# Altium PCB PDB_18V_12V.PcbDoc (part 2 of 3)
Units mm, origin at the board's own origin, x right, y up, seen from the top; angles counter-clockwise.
Board outline 185 x 160 mm, 4 copper layers (Top Layer, Int1 (GND), Int2 (GND), Bottom Layer), stack 1.636 mm thick; 209 components, 100 nets, 653 pads, 1413 vias.
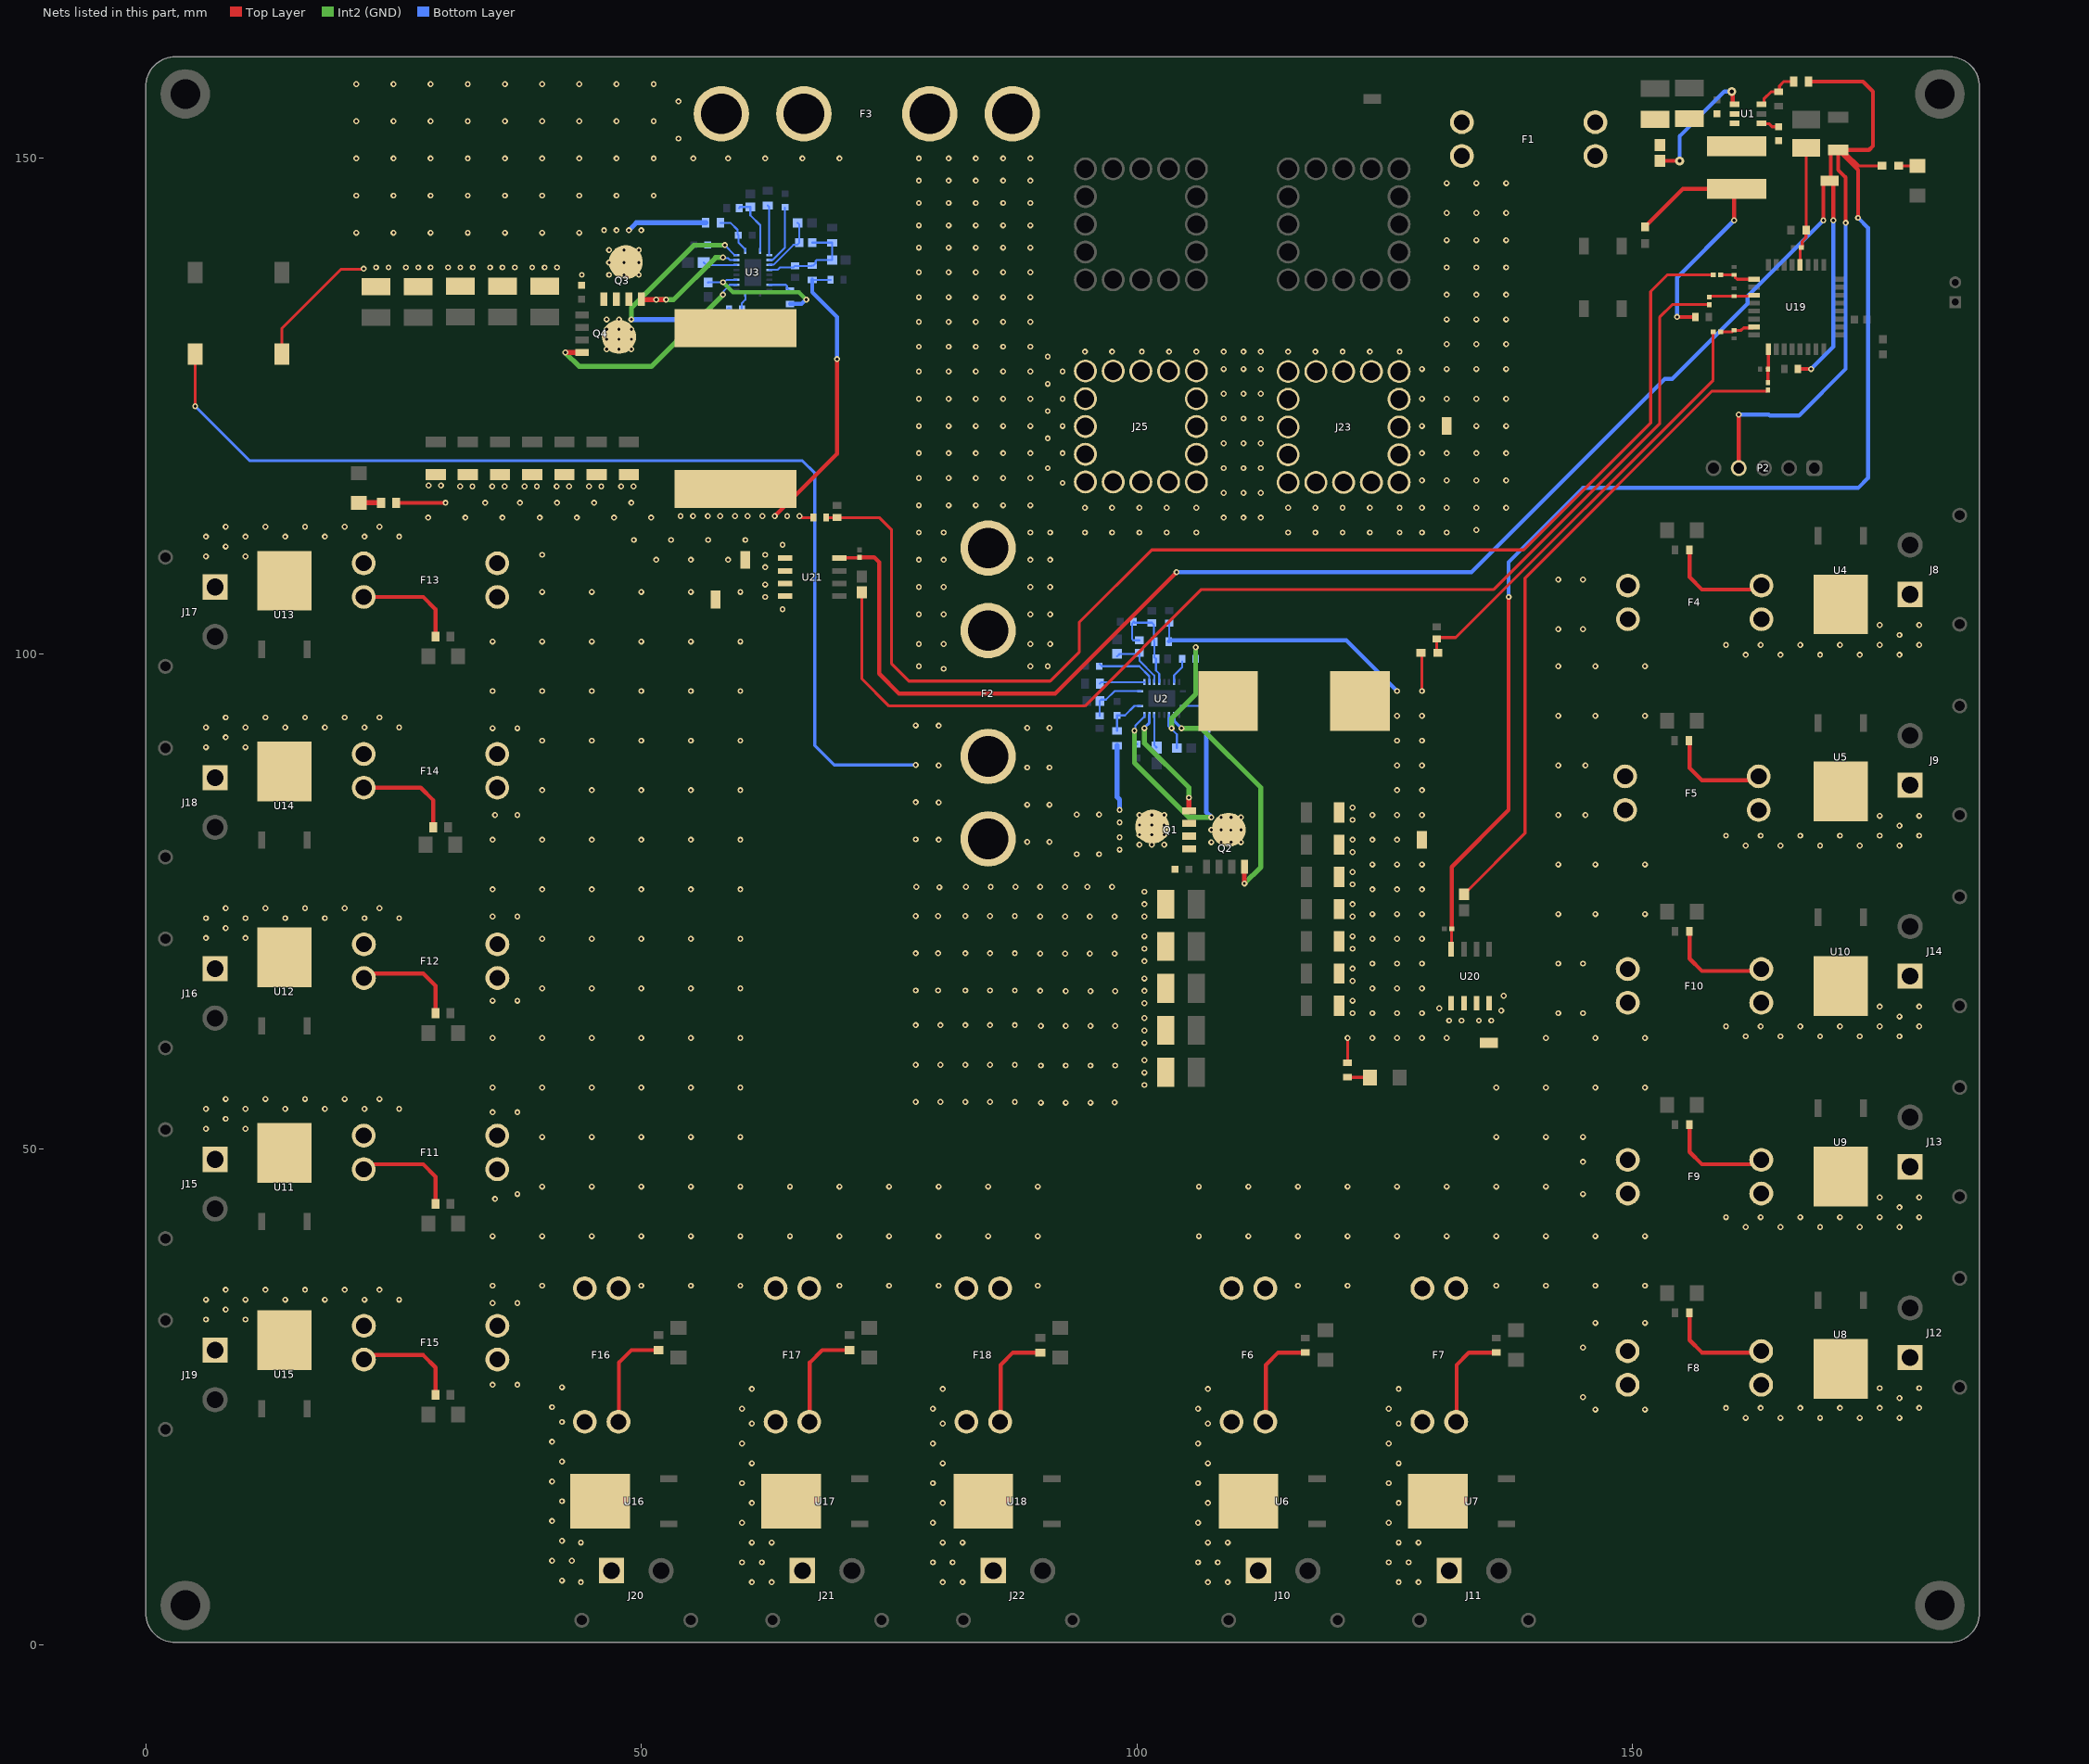
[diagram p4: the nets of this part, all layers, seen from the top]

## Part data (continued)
R3 R18: library part CMP-009-00259-1, "Fixed Resistor, Metal Glaze/thick Film, 0.1W, 140000ohm, 75V, 1% +/-Tol, 100ppm/Cel, Surface Mount, 0603", Case/Package=0603, Max Operating Temperature=155°C, Min Operating Temperature=-55°C, Power=100mW, Tolerance=1%
R5: library part CMP-009-00297-1, "CRCW FIXED RESISTOR 0603 (1608Metric) Chip Resistor ±1% ±100ppm/C 69.8kOhm 0.1W 1/10W", Case/Package=0603, Max Operating Temperature=155°C, Min Operating Temperature=-55°C, Tolerance=1%, Voltage Rating=75V
R6 R31 R32 R33 R34 R35 R36 R37: library part CMP-009-00285-1, "Res Thick Film 0603 1.6K Ohm 5% 1/10W ±200ppm/°C Molded SMD Paper T/R", Case/Package=0603, Max Operating Temperature=155°C, Min Operating Temperature=-55°C, Tolerance=5%, Voltage Rating=75V
R7 R21: library part CMP-009-00260-1, "Fixed Resistor, Thin Film, 0.1W, 7870ohm, 75V, 0.1% +/-Tol, 25ppm/Cel, Surface Mount, 0603", Case/Package=0603, Max Operating Temperature=155°C, Min Operating Temperature=-55°C, Power=100mW, Tolerance=0.1%
R8 R22: library part CMP-009-00279-1, "100mW Thick Film Resistors 75V ±100ppm/℃ ±1% 33.2kΩ 0603 Chip Resistor - Surface Mount ROHS", Case/Package=0603, Max Operating Temperature=155°C, Min Operating Temperature=-55°C, Tolerance=1%, Voltage Rating=75V
R9 R12 R25: library part CMP-009-00240-1, "Fixed Resistor, Metal Glaze/thick Film, 0.1W, 22100ohm, 75V, 1% +/-Tol, 100ppm/Cel, Surface Mount, 0603", Case/Package=0603, Max Operating Temperature=155°C, Min Operating Temperature=-55°C, Power=100mW, Tolerance=1%
R10 R11 R23 R24: library part CMP-009-00212-1, "Fixed Resistor, Metal Glaze/thick Film, 0.1W, 20000ohm, 75V, 1% +/-Tol, 100ppm/Cel, Surface Mount, 0603", Case/Package=0603, Max Operating Temperature=155°C, Min Operating Temperature=-55°C, Power=100mW, Tolerance=1%
R13: library part CMP-009-00251-1, "Fixed Resistor, Metal Glaze/thick Film, 0.1W, 165ohm, 75V, 1% +/-Tol, 100ppm/Cel, Surface Mount, 0603", Case/Package=0603, Max Operating Temperature=155°C, Min Operating Temperature=-55°C, Power=100mW, Tolerance=1%
R14 R29: library part CMP-009-00275-1, "Res Thick Film 0603 2.1 Ohm 1% 0.1W(1/10W) ±100ppm/C Molded SMD Automotive Paper T/R", Case/Package=0603, Max Operating Temperature=155°C, Min Operating Temperature=-55°C, Tolerance=1%, Voltage Rating=75V
R15 R28: library part CMP-009-00283-1, "Res Thick Film 0603 374 Ohm 1% 0.1W(1/10W) ±100ppm/C Pad SMD T/R", Case/Package=0603, Max Operating Temperature=155°C, Min Operating Temperature=-55°C, Tolerance=1%, Voltage Rating=75V
R16: library part CMP-009-00250-1, "Fixed Resistor, Thin Film, 0.1W, 4990ohm, 75V, 0.5% +/-Tol, 25ppm/Cel, Surface Mount, 0603", Case/Package=0603, Max Operating Temperature=155°C, Min Operating Temperature=-55°C, Power=100mW, Tolerance=0.5%
R17: library part CMP-009-00284-1, "Res Thick Film 0603 1.02K Ohm 1% 1/10W ±100ppm/°C Molded SMD SMD Paper T/R", Case/Package=0603, Max Operating Temperature=155°C, Min Operating Temperature=-55°C, Tolerance=1%, Voltage Rating=75V
R20 R38 R39 R40 R41 R42 R43 R44 R45: library part CMP-009-00263-1, "Fixed Resistor, Thin Film, 0.1W, 1000ohm, 75V, 0.1% +/-Tol, 50ppm/Cel, Surface Mount, 0603", Case/Package=0603, Max Operating Temperature=155°C, Min Operating Temperature=-55°C, Power=100mW, Tolerance=0.1%
R26: library part CMP-009-00287-1, "Res Thick Film 0603 158 Ohm 1% 0.1W(1/10W) ±100ppm/C Pad SMD T/R", Case/Package=0603, Max Operating Temperature=155°C, Min Operating Temperature=-55°C, Tolerance=1%, Voltage Rating=75V
R27: library part CMP-009-00197-1, "Fixed Resistor, Metal Glaze/thick Film, 0.33W, 7150ohm, 75V, 1% +/-Tol, 100ppm/Cel, Surface Mount, 0603", Case/Package=0603, Max Operating Temperature=155°C, Min Operating Temperature=-55°C, Power=250mW, Tolerance=1%
R30: library part CMP-009-00286-1, "Fixed Resistor, Metal Glaze/Thick Film, 0.1W, 1580ohm, 75V, 1% +/-Tol, Surface Mount, 0603", Case/Package=0603, Max Operating Temperature=155°C, Min Operating Temperature=-55°C, Tolerance=1%, Voltage Rating=75V
R46: library part CMP-009-00289-1, "Res Thick Film 0603 220 Ohm 5% 0.1W(1/10W) ±100ppm/C Pad SMD Automotive T/R", Case/Package=0603, Max Operating Temperature=155°C, Min Operating Temperature=-55°C, Tolerance=5%, Voltage Rating=75V
R47 R53: library part CMP-009-00288-1, "100mW Thick Film Resistors ±100ppm/℃ ±1% 10kΩ 0603 Chip Resistor - Surface Mount ROHS", Case/Package=0603, Max Operating Temperature=155°C, Min Operating Temperature=-55°C, Tolerance=1%, Voltage Rating=75V
R48: library part CMP-009-00294-1, "100mW Thick Film Resistors 75V ±100ppm/℃ ±5% 6.2kΩ 0603 Chip Resistor - Surface Mount ROHS", Case/Package=0603, Max Operating Temperature=155°C, Min Operating Temperature=-55°C, Tolerance=5%, Voltage Rating=50V
R49 R50: library part CMP-009-00293-1, "Res Thick Film 0603 2K Ohm 1% 1/10W ±100ppm/°C Molded SMD Punched Carrier T/R", Case/Package=0603, Max Operating Temperature=155°C, Min Operating Temperature=-55°C, Tolerance=1%, Voltage Rating=75V
R54 R55 R56 R57: library part CMP-009-00298-1, "Yageo RC0402FR-07150RL Resistor 0603 SMD 150 Ohm precision thick film", Case/Package=0402, Max Operating Temperature=155°C, Min Operating Temperature=-55°C, Tolerance=1%, Voltage Rating=50V
SW1 SW2: library part CMP-011-00016-1, "Slide Dip Switch, 1 Switches, SPST, Latched, 0.1A, 50VDC, Solder Terminal, Surface Mount-straight", Max Operating Temperature=85°C, Min Operating Temperature=-40°C
SW3: library part CMP-011-00018-1, "Switch Tactile OFF (ON) SPST Round Button Gull Wing 0.05A 24VDC 2.55N SMD T/R", Case/Package=SMD/SMT, Max Current Rating=20mA, Max Operating Temperature=85°C, Min Operating Temperature=-35°C
U1: library part CMP-00030-00008-3, "4V to 36V, 1A, 80-ÂµA Iq synchronous SIMPLE SWITCHERÂ® power converter 6-SOT-23 -40 to 125", Manufacturer_Name="Texas Instruments"
U2 U3: library part CMP-049-000000-3, "75V Synchronous Buck Controller With Wide Input Voltage and Duty Cycle Ranges 20-VQFN -40 to 125", Manufacturer_Name="Texas Instruments"
U4 U5 U6 U7 U8 U9 U10 U11 U12 U13 U14 U15 U16 U17 U18: library part CMP-004-00037-2, "Description", Manufacturer_Name="Diodes Inc"
U19: library part CMP-020-00027-1, "Microcontroller 32-bit ARM Cortex-M0+ RISC 64KB Flash 3.3V 32-Pin LQFP Tray", Case/Package=LQFP, Clock Frequency=48MHz, Frequency=64MHz, Max Operating Temperature=85°C, Max Supply Voltage=3.6V, Min Operating Temperature=-40°C, Min Supply Voltage=2V
U20 U21: library part CMP-056-000000-1, "AEC-Q100, Â±100-V isolated Hall-effect current sensor with internal reference 8-SOIC -40 to 125", Manufacturer_Name="Texas Instruments"

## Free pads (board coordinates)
  round 5 hole 3: 2(4,4) 2(4,156.5) 2(181,4) 2(181,156.5)

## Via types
v1: diameter 0.6, hole 0.3, Top Layer to Bottom Layer, 1411 vias
v2: diameter 0.9, hole 0.4, Top Layer to Bottom Layer, 2 vias

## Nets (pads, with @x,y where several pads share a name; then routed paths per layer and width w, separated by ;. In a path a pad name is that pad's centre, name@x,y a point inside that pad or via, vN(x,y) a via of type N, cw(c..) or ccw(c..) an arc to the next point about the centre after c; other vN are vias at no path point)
3.3V: C6.2 C7.2 C49.2 C50.2 C51.2 C52.2 J4.1 L1.1 P2.4 R2.1 R5.2 R11.2 R24.2 R53.2 U19.4 U20.8 U21.8 | length 377.5
  Top Layer w0.3: U21.8@69.974,109.655 70.022,109.702 71.953,109.702 C52.2@72,109.75 ; U20.8@131.71,70.198 131.734,70.222 131.734,72.226 C51.2@131.757,72.25 ; U19.4@166.9,139.25 166.9,140.914 166.986,141 C50.2@167.007,141 167.029,141 167.115,141.086 167.115,141.615 167.5,142 167.5,142.725 C49.2@167.525,142.75 167.525,151.05 C6.2@167.5,151.075 ; C7.2@171.568,150.507 172.825,149.25 R2.1@175.15,149.25
  Top Layer w0.4: C52.2@72,109.75 73.5,109.75 74,109.25 74,98 76,96 91.75,96 v1(104,108.25) ; C51.2@131.757,72.25 131.757,78.507 137.5,84.25 v1(137.5,105.75) ; R53.2@151.25,143.1 151.25,143.15 151.45,143.35 151.5,143.35 155.082,146.932 L1.1@160.5,146.932 160.25,146.682 v1(160.25,143.75) ; v1(154.5,134) R24.2@156.323,134 ; P2.4@160.71,118.75 v1(160.71,124.15) ; R11.2@166.677,128.75 v1(168,128.75) ; R5.2@167.75,157.75 173.25,157.75 174.25,156.75 174.25,151.25 173.85,150.85 C7.2@171.225,150.85 ; v1(169.25,143.75) 169.25,147.45 169.55,147.75 J4.1@169.87,147.75 169.95,147.75 170.25,147.45 v1(170.25,143.75) ; J4.1@170,147.75 170,150.5 170.35,150.85 C7.2@170.75,150.85 ; v1(171.5,143.5) 171.5,148.086 170.75,148.836 C7.2@170.75,150.85 ; v1(172.75,144) 172.75,148.85 C7.2@170.75,150.85
  Bottom Layer w0.4: v1(104,108.25) 133.75,108.25 153.25,127.75 154,127.75 161.606,135.356 161.606,136.106 v1(169.25,143.75) ; v1(137.5,105.75) 137.5,109.25 145,116.75 172.75,116.75 173.75,117.75 173.75,143 v1(172.75,144) ; v1(154.5,134) 154.5,138 v1(160.25,143.75) ; v1(160.71,124.15) 163.732,124.15 163.832,124.05 166.8,124.05 171.5,128.75 v1(171.5,143.5) ; v1(168,128.75) 170.25,131 v1(170.25,143.75)
3V3_CB: C1.1 U1.1 | length 1.9
  Top Layer w0.3: U1.1@163,153.55 163.045,153.505 163.76,153.505 164.065,153.2 C1.1@164.75,153.2
3V3_EN: R1.2 U1.4 | length 13.1
  Top Layer w0.4: R1.2@152.75,149.75 v2(154.75,149.75) ; v2(160,156.75) 160.096,156.654 160.096,155.529 160.175,155.45 U1.4@160.269,155.45
  Bottom Layer w0.4: v2(154.75,149.75) 154.75,152.25 159.25,156.75 v2(160,156.75)
3V3_FB: R5.1 R9.1 U1.3 | length 4.9
  Top Layer w0.3: U1.3@163,155.45 163.123,155.45 163.252,155.579 163.252,156.002 163.975,156.725 R9.1@164.75,156.725 164.824,156.799 164.824,157.324 165.25,157.75 166.025,157.75 166.25,157.975 R5.1@166.25,158
3V3_SW: C1.2 L1.2 U1.6
12V: C29.2 C30.2 C31.2 C32.2 C33.2 C34.2 C35.2 J7.1 L3.2 R20.1 R25.1 R26.2 R48.2 U21.1 U21.2 | length 35.8
  Top Layer w0.3: v1(65.967,113.901) 66.048,113.901 66.199,113.75 R48.2@67.35,113.75
  Top Layer w0.4: R20.1@25.25,115.25 v1(30.25,115.25) ; v1(63.467,113.901) 69.75,120.184 v1(69.75,129.75)
  Bottom Layer w0.2: R25.1@67.25,137.75 R26.2@69.1,137.75
  Bottom Layer w0.4: R25.1@67.25,137.75 67.25,136.5 69.75,134 v1(69.75,129.75)
  other v1: 62.5,108.75 51.5,109.5 55,109.5 58.75,109.5 62.5,110 64.25,111 49.25,111.5 53,111.5 56.75,111.5 60.5,111.5 28.5,113.75 32.25,113.75 36,113.75 39.75,113.75 43.5,113.75 47.25,113.75 51,113.75 53.967,113.901 55.217,113.901 56.717,113.901 57.967,113.901 59.467,113.901 60.717,113.901 62.217,113.901 64.717,113.901 34.25,115.25 37.75,115.25 41.5,115.25 45.25,115.25 49,115.25 31.717,116.901 32.967,116.901 34.967,116.901 36.217,116.901 38.217,116.901 39.467,116.901 41.467,116.901 42.717,116.901 44.717,116.901 45.967,116.901 47.967,116.901 49.217,116.901 28.545,116.991 29.795,116.991
12V_Fans: F15.2_1 F15.2_2 J19.P R42.2 U15.3 | length 10.5
  Top Layer w0.4: F15.2_1@22,29.25 28,29.25 29.25,28 R42.2@29.25,25.25
  other v1: 6.078,32.839 10.078,32.839 8.078,33.839 6.078,34.839 10.078,34.839 14.078,34.839 18.078,34.839 22.078,34.839 25.578,34.839 8.078,35.839 12.078,35.839 16.078,35.839 20.078,35.839 23.578,35.839
12V_PTZ: F12.2_1 F12.2_2 J16.P R39.2 U12.3 | length 10.5
  Top Layer w0.4: F12.2_1@22,67.75 28,67.75 29.25,66.5 R39.2@29.25,63.75
  other v1: 6.078,71.339 10.078,71.339 8.078,72.339 6.078,73.339 10.078,73.339 14.078,73.339 18.078,73.339 22.078,73.339 25.578,73.339 8.078,74.339 12.078,74.339 16.078,74.339 20.078,74.339 23.578,74.339
12V_RoverLab1: F13.2_1 F13.2_2 J17.P R40.2 U13.3 | length 10.5
  Top Layer w0.4: F13.2_1@22,105.75 28,105.75 29.25,104.5 R40.2@29.25,101.75
  other v1: 6.078,109.839 10.078,109.839 8.078,110.839 6.078,111.839 10.078,111.839 14.078,111.839 18.078,111.839 22.078,111.839 25.578,111.839 8.078,112.839 12.078,112.839 16.078,112.839 20.078,112.839 23.578,112.839
12V_RoverLab2: F14.2_1 F14.2_2 J18.P R41.2 U14.3 | length 10.5
  Top Layer w0.4: F14.2_1@21.75,86.5 27.75,86.5 29,85.25 R41.2@29,82.5
  other v1: 6.078,90.589 10.078,90.589 8.078,91.589 6.078,92.589 10.078,92.589 14.078,92.589 18.078,92.589 22.078,92.589 25.578,92.589 8.078,93.589 12.078,93.589 16.078,93.589 20.078,93.589 23.578,93.589
12V_S: F11.1_1 F11.1_2 F12.1_1 F12.1_2 F13.1_1 F13.1_2 F14.1_1 F14.1_2 F15.1_1 F15.1_2 F16.1_1 F16.1_2 F17.1_1 F17.1_2 F18.1_1 F18.1_2 J3.1 U21.3 U21.4
  other v1: 35,26.25 37.5,26.25 35,34.5 37.5,34.5 35,36.25 40,36.25 50,36.25 55,36.25 60,36.25 70,36.25 75,36.25 80,36.25 90,36.25 35,41.25 40,41.25 45,41.25 50,41.25 55,41.25 60,41.25 65,41.25 70,41.25 75,41.25 80,41.25 85,41.25 90,41.25 35.25,45 37.5,45.5 40,46.25 45,46.25 50,46.25 55,46.25 60,46.25 65,46.25 70,46.25 75,46.25 80,46.25 85,46.25 90,46.25 40,51.25 45,51.25 50,51.25 55,51.25 60,51.25 35,53.75 37.5,53.75 35,56.25 40,56.25 45,56.25 50,56.25 55,56.25 60,56.25 35,61.25 40,61.25 45,61.25 50,61.25 55,61.25 60,61.25 35,65 37.5,65 40,66.25 45,66.25 50,66.25 55,66.25 60,66.25 40,71.25 45,71.25 50,71.25 55,71.25 60,71.25 35,73.5 37.5,73.5 35,76.25 40,76.25 45,76.25 50,76.25 55,76.25 60,76.25 35,81.25 40,81.25 45,81.25 50,81.25 55,81.25 60,81.25 35.25,83.75 37.5,83.75 40,86.25 45,86.25 50,86.25 55,86.25 60,86.25 40,91.25 45,91.25 50,91.25 55,91.25 60,91.25 35,92.5 37.5,92.5 35,96.25 40,96.25 45,96.25 50,96.25 55,96.25 60,96.25 35,101.25 40,101.25 45,101.25 50,101.25 55,101.25 60,101.25 64.25,104.5 62.5,105.75 40,106.25 45,106.25 50,106.25 55,106.25 60,106.25 62.5,107 40,110
12V_Spare1: F16.2_1 F16.2_2 J20.P R43.2 U16.3 | length 10.5
  Top Layer w0.4: F16.2_1@47.75,22.5 47.75,28.5 49,29.75 R43.2@51.75,29.75
  other v1: 43.911,6.328 42,6.5 41,8.5 43,8.5 43.911,10.328 42,10.5 41,12.5 42,14.5 41,16.5 42,18.5 41,20.5 42,22.5 41,24 42,26
12V_Spare2: F17.2_1 F17.2_2 J21.P R44.2 U17.3 | length 10.5
  Top Layer w0.4: F17.2_1@67,22.5 67,28.5 68.25,29.75 R44.2@71,29.75
  other v1: 61.161,6.328 63.161,6.328 60.161,8.328 62.161,8.328 61.161,10.328 63.161,10.328 60.161,12.328 61.161,14.328 60.161,16.328 61.161,18.328 60.161,20.328 61.161,22.328 60.161,23.828 61.161,25.828
12V_Spare3: F18.2_1 F18.2_2 J22.P R45.2 U18.3 | length 10.5
  Top Layer w0.4: F18.2_1@86.25,22.25 86.25,28.25 87.5,29.5 R45.2@90.25,29.5
  other v1: 80.411,6.328 82.411,6.328 79.411,8.328 81.411,8.328 80.411,10.328 82.411,10.328 79.411,12.328 80.411,14.328 79.411,16.328 80.411,18.328 79.411,20.328 80.411,22.328 79.411,23.828 80.411,25.828
12V_USB_HUB: F11.2_1 F11.2_2 J15.P R38.2 U11.3 | length 10.5
  Top Layer w0.4: F11.2_1@22,48.5 28,48.5 29.25,47.25 R38.2@29.25,44.5
  other v1: 6.078,52.089 10.078,52.089 8.078,53.089 6.078,54.089 10.078,54.089 14.078,54.089 18.078,54.089 22.078,54.089 25.578,54.089 8.078,55.089 12.078,55.089 16.078,55.089 20.078,55.089 23.578,55.089
18V: C8.2 C9.2 C10.2 C11.2 C12.2 C13.2 C14.2 J5.1 L2.2 R6.1 R12.1 R13.1 R47.2 U20.1 U20.2 | length 33.5
  Top Layer w0.3: R6.1@121.25,58.725 v1(121.25,61.25) ; R47.2@128.65,100.125 128.75,100.025 v1(128.75,96.25)
  Bottom Layer w0.2: R12.1@103.225,101.25 103.25,101.275 R13.1@103.25,103.125
  Bottom Layer w0.4: R12.1@103.225,101.25 103.225,101.252 103.35,101.377 121.123,101.377 v1(126.25,96.25)
  other v1: 123.75,61.25 126.25,61.25 128.75,61.25 131.25,61.25 131.5,63 132.75,63 121.75,63.75 123.75,63.75 126.25,63.75 128.75,63.75 130.5,64.25 121.75,65 123.75,66.25 126.25,66.25 128.75,66.25 121.75,67 121.75,68.25 123.75,68.75 126.25,68.75 128.75,68.75 121.75,70.25 123.75,71.25 126.25,71.25 128.75,71.25 121.75,71.5 121.75,73.5 123.75,73.75 126.25,73.75 128.75,73.75 121.75,74.75 123.75,76.25 126.25,76.25 128.75,76.25 121.75,76.75 121.75,78 123.75,78.75 126.25,78.75 128.75,78.75 121.75,80 121.75,81.25 123.75,81.25 126.25,81.25 121.75,83.25 123.75,83.75 126.25,83.75 128.75,83.75 121.75,84.5 126.25,86.25 128.75,86.25 126.25,88.75 128.75,88.75 126.25,91.25 128.75,91.25 126.25,93.75 128.75,93.75
18V_JETSON: F5.2_1 F5.2_2 J9.P R32.2 U5.3 | length 10.5
  Top Layer w0.4: R32.2@155.75,91.25 155.75,88.5 157,87.25 F5.2_1@163,87.25
  other v1: 161.422,80.661 164.922,80.661 168.922,80.661 172.922,80.661 176.922,80.661 159.422,81.661 162.922,81.661 166.922,81.661 170.922,81.661 174.922,81.661 178.922,81.661 176.922,82.661 174.922,83.661 178.922,83.661
18V_NUC: F4.2_1 F4.2_2 J8.P R31.2 U4.3 | length 10.5
  Top Layer w0.4: R31.2@155.75,110.5 155.75,107.75 157,106.5 F4.2_1@163,106.5
  other v1: 161.422,99.911 164.922,99.911 168.922,99.911 172.922,99.911 176.922,99.911 159.422,100.911 162.922,100.911 166.922,100.911 170.922,100.911 174.922,100.911 178.922,100.911 176.922,101.911 174.922,102.911 178.922,102.911
18V_S: F4.1_1 F4.1_2 F5.1_1 F5.1_2 F6.1_1 F6.1_2 F7.1_1 F7.1_2 F8.1_1 F8.1_2 F9.1_1 F9.1_2 F10.1_1 F10.1_2 J6.1 U20.3 U20.4
  other v1: 146.25,23.75 151.25,23.75 145,25 145,30 146.25,32.5 151.25,32.5 116.25,36.25 121.25,36.25 136.25,36.25 141.25,36.25 146.25,36.25 151.25,36.25 106.25,41.25 111.25,41.25 116.25,41.25 121.25,41.25 126.25,41.25 131.25,41.25 136.25,41.25 141.25,41.25 146.25,41.25 151.25,41.25 145,45.5 106.25,46.25 111.25,46.25 116.25,46.25 121.25,46.25 126.25,46.25 131.25,46.25 136.25,46.25 141.25,46.25 145,48.75 136.25,51.25 141.25,51.25 145,51.25 136.25,56.25 141.25,56.25 146.25,56.25 151.25,56.25 141.25,61.25 146.25,61.25 151.25,61.25 134.5,63 135.75,63 142.5,63.75 145,63.75 136.75,64 137,65.5 142.5,68.75 145,68.75 142.5,73.75 146.25,73.75 151.25,73.75 142.5,78.75 146.25,78.75 151.25,78.75 142.5,83.75 145.25,83.75 142.5,88.75 145.25,88.75 142.5,93.75 146.25,93.75 151.25,93.75 142.5,98.75 146.25,98.75 151.25,98.75 142.5,102.5 145,102.5 142.5,107.5 145,107.5
18V_Spare1: F6.2_1 F6.2_2 J10.P R33.2 U6.3 | length 10.5
  Top Layer w0.4: F6.2_1@113,22.25 113,28.25 114.25,29.5 R33.2@117,29.5
  other v1: 107.161,6.328 109.161,6.328 106.161,8.328 108.161,8.328 107.161,10.328 109.161,10.328 106.161,12.328 107.161,14.328 106.161,16.328 107.161,18.328 106.161,20.328 107.161,22.328 106.161,23.828 107.161,25.828
18V_Spare2: F7.2_1 F7.2_2 J11.P R34.2 U7.3 | length 10.5
  Top Layer w0.4: F7.2_1@132.25,22.25 132.25,28.25 133.5,29.5 R34.2@136.25,29.5
  other v1: 126.411,6.328 128.411,6.328 125.411,8.328 127.411,8.328 126.411,10.328 128.411,10.328 125.411,12.328 126.411,14.328 125.411,16.328 126.411,18.328 125.411,20.328 126.411,22.328 125.411,23.828 126.411,25.828
18V_Spare3: F8.2_1 F8.2_2 J12.P R35.2 U8.3 | length 10.5
  Top Layer w0.4: R35.2@155.75,33.5 155.75,30.75 157,29.5 F8.2_1@163,29.5
  other v1: 161.422,22.911 164.922,22.911 168.922,22.911 172.922,22.911 176.922,22.911 159.422,23.911 162.922,23.911 166.922,23.911 170.922,23.911 174.922,23.911 178.922,23.911 176.922,24.911 174.922,25.911 178.922,25.911
18V_Spare4: F9.2_1 F9.2_2 J13.P R36.2 U9.3 | length 10.5
  Top Layer w0.4: R36.2@155.75,52.5 155.75,49.75 157,48.5 F9.2_1@163,48.5
  other v1: 161.422,42.161 164.922,42.161 168.922,42.161 172.922,42.161 176.922,42.161 159.422,43.161 162.922,43.161 166.922,43.161 170.922,43.161 174.922,43.161 178.922,43.161 176.922,44.161 174.922,45.161 178.922,45.161
18V_Spare5: F10.2_1 F10.2_2 J14.P R37.2 U10.3 | length 10.5
  Top Layer w0.4: R37.2@155.75,72 155.75,69.25 157,68 F10.2_1@163,68
  other v1: 161.422,61.411 164.922,61.411 168.922,61.411 172.922,61.411 176.922,61.411 159.422,62.411 162.922,62.411 166.922,62.411 170.922,62.411 174.922,62.411 178.922,62.411 176.922,63.411 174.922,64.411 178.922,64.411
24V: F1.1_1 F1.1_2 F2.1_1 F2.1_2 F3.1_1 F3.1_2 J1.1 J23.1 J23.2 J23.3 J23.4 J23.5 J23.6 J23.7 J23.8 J23.9 J23.10 J23.11 J23.12 J23.13 J23.14 J23.15 J23.16 J25.1 J25.2 J25.3 J25.4 J25.5 J25.6 J25.7 J25.8 J25.9 J25.10 J25.11 J25.12 J25.13 J25.14 J25.15 J25.16
  other v1: 80.5,98.5 78,98.75 89.25,98.75 91,98.75 78,101 80.5,101 89.25,101 91.25,101 78,104 80.5,104 89.25,104 91.25,104 78,106.75 80.5,106.75 89.25,106.75 91.25,106.75 78,109.5 80.5,109.5 89.25,109.5 91.25,109.5 78,112.25 80.5,112.25 89.25,112.25 91.25,112.25 94.75,112.25 97.5,112.25 100.25,112.25 103,112.25 106,112.25 115.25,112.25 118,112.25 120.75,112.25 123.5,112.25 126.5,112.25 128.75,112.25 131.25,112.25 134.25,112.5 108.75,113.75 110.75,113.75 112.5,113.75 94.75,114.75 97.5,114.75 100.25,114.75 103,114.75 106,114.75 115.25,114.75 118,114.75 120.75,114.75 123.5,114.75 126.5,114.75 128.75,114.75 131.25,114.75 134.25,114.75 137.25,114.75 78,115 81,115 83.75,115 86.5,115 89.25,115 108.75,116.25 110.75,116.25 112.5,116.25 92.5,117.25 128.75,117.5 131.25,117.5 134.25,117.5 137.25,117.5 78,117.75 81,117.75 83.75,117.75 86.5,117.75 89.25,117.75 91,118.75 108.75,118.75 110.75,118.75 112.5,118.75 78,120.25 81,120.25 83.75,120.25 86.5,120.25 89.25,120.25 92.5,120.25 128.75,120.25 131.25,120.25 134.25,120.25 137.25,120.25 108.75,121.25 110.75,121.25 112.5,121.25 91,121.75 78,123 81,123 83.75,123 86.5,123 89.25,123 92.5,123 128.75,123 134.25,123 137.25,123 108.75,123.75 110.75,123.75 112.5,123.75 91,124.5 78,125.75 81,125.75 83.75,125.75 86.5,125.75 89.25,125.75 92.5,125.75 128.75,125.75 131.25,125.75 134.25,125.75 137.25,125.75 108.75,126.25 110.75,126.25 112.5,126.25 91,127.25 78,128.5 81,128.5 83.75,128.5 86.5,128.5 89.25,128.5 92.5,128.5 108.75,128.75 110.75,128.75 112.5,128.75 128.75,128.75 131.25,128.75 134.25,128.75 137.25,128.75 91,130 94.75,130.5 97.5,130.5 100.5,130.5 103.25,130.5 106,130.5 108.75,130.5 110.75,130.5 112.5,130.5 115.25,130.5 118,130.5 120.75,130.5 123.5,130.5 126.5,130.5 78,131 81,131 83.75,131 86.5,131 89.25,131 131.25,131.25 134.25,131.25 137.25,131.25 78,133.5 81,133.5 83.75,133.5 86.5,133.5 89.25,133.5 131.25,133.75 134.25,133.75 137.25,133.75 78,136 81,136 83.75,136 86.5,136 89.25,136 131.25,136.25 134.25,136.25 137.25,136.25 78,138.5 81,138.5 83.75,138.5 86.5,138.5 89.25,138.5 131.25,139 134.25,139 137.25,139 78,141 81,141 83.75,141 86.5,141 89.25,141 131.25,141.75 134.25,141.75 137.25,141.75 78,143.25 81,143.25 83.75,143.25 86.5,143.25 89.25,143.25 131.25,144.5 134.25,144.5 137.25,144.5 78,145.5 81,145.5 83.75,145.5 86.5,145.5 89.25,145.5 131.25,147.5 134.25,147.5 137.25,147.5 78,147.75 81,147.75 83.75,147.75 86.5,147.75 89.25,147.75 78,150 81,150 83.75,150 86.5,150 89.25,150
24V_BUCK: C3.1 C4.1 C5.2 F1.2_1 F1.2_2 R1.1 U1.5
24V_BUCK12: C42.1 C43.1 C44.1 C45.1 C46.1 C47.1 F3.2_1 F3.2_2 Q3.5-6-7-8 R29.1 SW2.1 | length 21.4
  Top Layer w0.3: SW2.1@13.75,130.25 13.75,132.871 19.693,138.814 21.943,138.814 v1(22,138.871)
  Bottom Layer w0.5: v1(48.75,142.75) 49.5,143.5 R29.1@56.5,143.5
  other v1: 44,138.25 46.75,138.25 48.25,138.25 49.75,138.25 23.25,139 24.5,139 26.25,139 27.5,139 28.75,139 30.5,139 31.75,139 33,139 34.75,139 36,139 37.25,139 39,139 40.25,139 41.5,139 46.75,139.5 48.25,139.5 49.75,139.5 46.75,140.75 48.25,140.75 49.75,140.75 21.25,142.5 25,142.5 28.75,142.5 32.5,142.5 36.25,142.5 40,142.5 43.75,142.5 46.25,142.75 47.5,142.75 50,142.75 21.25,146.25 25,146.25 28.75,146.25 32.5,146.25 36.25,146.25 40,146.25 43.75,146.25 47.5,146.25 51.25,146.25 21.25,150 25,150 28.75,150 32.5,150 36.25,150 40,150 43.75,150 47.5,150 51.25,150 55.25,150 58.75,150 62.5,150 66.25,150 70,150 53.75,152 21.25,153.75 25,153.75 28.75,153.75 32.5,153.75 36.25,153.75 40,153.75 43.75,153.75 47.5,153.75 51.25,153.75 53.75,155.75 21.25,157.5 25,157.5 28.75,157.5 32.5,157.5 36.25,157.5 40,157.5 43.75,157.5 47.5,157.5 51.25,157.5
24V_BUCK18: C19.1 C20.1 C21.1 C22.1 C23.1 C24.1 F2.2_1 F2.2_2 Q1.5-6-7-8 R14.1 SW1.1 | length 115.6
  Top Layer w0.3: v1(5,125) SW1.1@5,130.25
  Bottom Layer w0.3: v1(5,125) 10.5,119.5 66.25,119.5 67.5,118.25 67.5,90.75 69.462,88.788 v1(77.685,88.788)
  Bottom Layer w0.5: R14.1@98,90.75 98,85.55 98.25,85.3 v1(98.25,84.25)
  other v1: 90.315,54.712 92.815,54.712 95.315,54.712 97.75,54.75 77.685,54.788 80.185,54.788 82.685,54.788 85.185,54.788 87.685,54.788 100.75,56.5 100.75,57.75 90.315,58.462 92.815,58.462 95.315,58.462 97.815,58.462 77.685,58.538 80.185,58.538 82.685,58.538 85.185,58.538 87.685,58.538 100.75,59 100.75,60.75 100.75,62 90.315,62.462 92.815,62.462 95.315,62.462 97.815,62.462 77.685,62.538 80.185,62.538 82.685,62.538 85.185,62.538 87.685,62.538 100.75,63.25 100.75,64.75 92.815,65.962 95.315,65.962 97.815,65.962 90.25,66 100.75,66 77.685,66.038 79.935,66.038 82.685,66.038 85.185,66.038 87.685,66.038 100.75,67.25 100.75,69 90.25,69.75 92.75,69.75 95.25,69.75 97.75,69.75 77.685,69.788 79.935,69.788 82.685,69.788 85.185,69.788 87.685,69.788 100.75,70.25 100.75,71.5 90.25,73.5 92.75,73.5 95.25,73.5 97.75,73.5 100.75,73.5 77.685,73.538 79.935,73.538 82.685,73.538 85.185,73.538 87.685,73.538 100.75,74.75 100.75,76 80.065,76.462 77.75,76.5 82.75,76.5 85.25,76.5 87.75,76.5 90.25,76.5 92.75,76.5 95,76.5 97.5,76.5 93.935,79.788 96.185,79.788 98.25,80.25 100.25,80.75 101.5,80.75 102.75,80.75 88.935,81.038 91.185,81.038 80,81.25 77.685,81.288 98.25,81.5 100.25,81.75 101.5,81.75 102.75,81.75 100.25,82.75 101.5,82.75 102.75,82.75 98.25,83 100.25,83.75 101.5,83.75 102.75,83.75 93.935,83.788 96.185,83.788 88.935,84.788 91.185,84.788 80,85 77.685,85.038 88.935,88.538 91.185,88.538 80,88.75 88.935,92.538 91.185,92.538 80,92.75 77.685,92.788
B3.3V_LED: D1.2 R2.2 | length 1.9
  Top Layer w0.3: R2.2@176.85,149.25 D1.2@178.75,149.25
B12_Current: C56.2 R57.2 U19.11 | length 4.6
  Top Layer w0.3: R57.2@157.75,136 157.75,136.025 157.825,136.1 C56.2@160.25,136.1 161.8,136.1 161.9,136.2 U19.11@162.25,136.2
B12_Current_In: R52.2 R57.1 | length 118.2
  Top Layer w0.3: R52.2@72.25,106.199 72.25,97.5 75,94.75 94.75,94.75 106.5,106.5 136,106.5 152.75,123.25 152.75,134 154,135.25 R57.1@157.563,135.25
B12_Voltage: C54.2 R55.2 U19.9 | length 3.7
  Top Layer w0.3: R55.2@158.875,138.25 160.3,138.25 160.35,138.2 160.35,138 160.55,137.8 U19.9@162.25,137.8
B12_Voltage_In: R48.1 R50.2 R55.1 | length 130.7
  Top Layer w0.3: R48.1@68.65,113.75 R50.2@69.75,113.75 74,113.75 75.25,112.5 75.25,99 77,97.25 91.25,97.25 94.175,100.175 94.175,103.175 101.5,110.5 139,110.5 151.817,123.317 151.817,136.567 153.5,138.25 R55.1@158.125,138.25
B12V_BST: R19.1 U3.17 | length 3.4
  Bottom Layer w0.2: R19.1@56.301,139.5 56.551,139.25 U3.17@59.6,139.25
B12V_COMP: C38.1 C41.1 U3.4 | length 6.1
  Bottom Layer w0.2: U3.4@62.9,139.25 62.92,139.27 63.33,139.27 65.342,141.282 65.732,141.282 C41.1@65.95,141.5 65.95,143.324 C38.1@65.774,143.5
B12V_EN: R18.2 R21.1 U3.1 | length 6
  Bottom Layer w0.2: R18.2@59.875,145 59.975,145.1 R21.1@61,145.1 61,144.25 62,143.25 U3.1@62,140.65
B12V_FB: C39.1 C41.2 R25.2 R27.2 R30.2 U3.5 | length 10.6
  Bottom Layer w0.2: U3.5@62.9,138.75 62.92,138.77 63.77,138.77 64,139 65.35,139 R30.2@65.5,139.15 67.2,139.15 R25.2@67.25,139.2 67.375,139.2 67.6,139.425 67.6,139.633 67.717,139.75 C39.1@69.25,139.75 R27.2@69.25,141.5 C41.2@67.25,141.5
B12V_HO: Q3.4 U3.18 | length 12.4
  Top Layer w0.5: Q3.4@50.02,135.75 v1(51.5,135.75) v1(52.5,135.75)
  Int2 (GND) w0.5: v1(51.5,135.75) v1(52.5,135.75) 53.25,135.75 57.5,140 v1(58.25,140)
  Bottom Layer w0.2: v1(58.25,140) 58.327,139.923 58.777,139.923 58.95,139.75 U3.18@59.6,139.75
B12V_ILIM: C40.1 R28.1 U3.11 | length 3.5
  Bottom Layer w0.2: C40.1@60.124,133 60.124,134.724 R28.1@60.15,134.75 60.15,135.4 60.5,135.75 U3.11@60.5,136.35
B12V_LED: D3.2 R20.2 | length 2.3
  Top Layer w0.5: D3.2@21.5,115.25 R20.2@23.75,115.25
B12V_LO: Q4.4 U3.13 | length 23.1
  Top Layer w0.5: v1(42.338,130.412) Q4.4@44.021,130.412
  Int2 (GND) w0.5: v1(42.338,130.412) 43.75,129 51,129 v1(58.25,136.25)
  Bottom Layer w0.2: v1(58.25,136.25) 58.324,136.324 58.324,136.624 58.95,137.25 U3.13@59.6,137.25
B12V_RT: R22.2 U3.2 | length 5.1
  Bottom Layer w0.2: R22.2@62.75,145.25 62.9,145.1 U3.2@62.9,140.25
B12V_SS: C36.2 U3.3 | length 6.1
  Bottom Layer w0.2: U3.3@62.9,139.75 63.08,139.75 63.1,139.77 63.264,139.77 64.5,141.006 C36.2@64.5,145.025
B12V_SW: C28.2 L3.1 Q3.1 Q3.2 Q3.3 Q4.5-6-7-8 R28.2 U3.19 | length 27.2
  Int2 (GND) w0.5: v1(49,133.75) 49,134.939 55.311,141.25 v1(58.42,141.25)
  Bottom Layer w0.2: C28.2@56.7,141.25 v1(58.42,141.25) 59.42,140.25 U3.19@59.6,140.25
  Bottom Layer w0.5: v1(49,133.75) 58.499,133.75 58.8,134.051 58.8,134.7 R28.2@58.85,134.75
  other v1: 46.5,130.75 47.75,130.75 49,130.75 46.5,131.75 47.75,131.75 49,131.75 46.5,132.75 47.75,132.75 49,132.75 46.5,133.75 47.75,133.75
B12V_SYNCIN: R23.2 U3.8 | length 2.5
  Bottom Layer w0.2: U3.8@62.9,137.25 64.579,137.25 64.696,137.133 64.696,136.906 64.926,136.677 R23.2@65,136.677
B12V_VCC: C37.2 R23.1 U3.14 | length 13.9
  Int2 (GND) w0.4: v1(58.25,137.5) 59.25,136.5 65.901,136.5 v1(66.651,135.75)
  Bottom Layer w0.2: C37.2@56.75,137.477 56.773,137.5 58.358,137.5 58.608,137.75 U3.14@59.6,137.75
  Bottom Layer w0.4: R23.1@65,135.323 66.17,135.323 66.596,135.75 v1(66.651,135.75)
B12V_VIN: C48.1 R29.2 U3.20 | length 4.5
  Bottom Layer w0.2: R29.2@58,143.5 59,143.5 59.717,142.783 59.717,142.333 C48.1@59.8,142.25 59.8,141.53 60.5,140.83 U3.20@60.5,140.65
B18_Current: C55.2 R56.2 U19.17 | length 3.4
  Top Layer w0.3: C55.2@163.55,128.8 163.7,128.95 U19.17@163.7,130.75 ; R56.2@163.65,127.375 C55.2@163.65,128.75
B18_Current_In: R51.2 R56.1 | length 66.8
  Top Layer w0.3: R51.2@133,75.75 139.15,81.9 139.15,107.65 158.025,126.525 163.575,126.525 163.65,126.6 R56.1@163.65,126.625
B18_Voltage: C53.2 R54.2 U19.15 | length 3.6
  Top Layer w0.3: R54.2@158.875,132.5 160.05,132.5 160.2,132.65 C53.2@160.25,132.65 160.95,132.65 161.2,132.9 162.15,132.9 U19.15@162.25,133
B18_Voltage_In: R47.1 R49.2 R54.1 | length 45
  Top Layer w0.3: R47.1@130.35,100.125 130.25,100.225 R49.2@130.25,101.5 130.406,101.656 132.156,101.656 158.125,127.625 R54.1@158.125,132.5
B18V_BST: R4.1 U2.17 | length 3.4
  Bottom Layer w0.2: U2.17@101.75,93.85 101.75,90.801 R4.1@102,90.551
B18V_COMP: C17.1 C27.1 U2.4 | length 6
  Bottom Layer w0.2: C17.1@98,99.75 98.25,100 100.126,100 C27.1@100.25,100.124 100.25,99.335 101.75,97.835 U2.4@101.75,97.15
B18V_EN: R3.2 R7.1 U2.1 | length 6
  Bottom Layer w0.2: R3.2@96.25,93.75 R7.1@96.25,95.25 96.383,95.383 96.883,95.383 97.75,96.25 U2.1@100.35,96.25
B18V_FB: C18.1 C27.2 R12.2 R16.2 R17.2 U2.5 | length 10.8
  Bottom Layer w0.2: C27.2@100.25,101.376 99.624,101.376 99.5,101.5 99.5,103.073 R16.2@99.677,103.25 99.777,103.15 C18.1@101.5,103.15 101.725,102.925 101.725,101.3 R12.2@101.775,101.25 101.775,99.65 R17.2@101.925,99.5 101.925,98.325 102.25,98 U2.5@102.25,97.15
B18V_HO: Q1.4 U2.18 | length 11.8
  Top Layer w0.5: v1(105.25,85.5) 105.25,84.16 105.255,84.155 Q1.4@105.32,84.155
  Int2 (GND) w0.5: v1(100.75,92.5) 100.75,91 105.25,86.5 v1(105.25,85.5)
  Bottom Layer w0.3: v1(100.75,92.5) 100.75,92.561 101.25,93.061 U2.18@101.25,93.85
B18V_ILIM: C26.1 R15.1 U2.11 | length 4.9
  Bottom Layer w0.2: U2.11@104.65,94.75 106.5,94.75 107,94.25 R15.1@107,93.65 108.724,93.65 C26.1@108.75,93.624
B18V_LED: D2.2 R6.2 | length 2.3
  Top Layer w0.3: R6.2@121.25,57.275 123.475,57.275 D2.2@123.5,57.25
B18V_LO: Q2.4 U2.13 | length 24.2
  Top Layer w0.5: v1(110.837,76.837) Q2.4@110.837,78.521
  Int2 (GND) w0.5: v1(104.5,92.5) 106.5,92.5 112.5,86.5 112.5,78.5 v1(110.837,76.837)
  Bottom Layer w0.3: U2.13@103.75,93.85 103.75,93.25 v1(104.5,92.5)
B18V_RT: R8.2 U2.2 | length 4.6
  Bottom Layer w0.2: R8.2@96.25,97 96.4,97.15 U2.2@100.75,97.15
B18V_SS: C15.1 U2.3 | length 6.1
  Bottom Layer w0.2: C15.1@96.25,99 96.25,98.975 96.475,98.75 100.25,98.75 101.25,97.75 U2.3@101.25,97.15
B18V_SW: C2.2 L2.1 Q1.1 Q1.2 Q1.3 Q2.5-6-7-8 R15.2 U2.19 | length 25.8
  Int2 (GND) w0.5: v1(99.75,92.25) 99.75,89 105.25,83.5 v1(107.5,83.5)
  Bottom Layer w0.2: C2.2@100,90.9 99.75,91.15 v1(99.75,92.25) 99.827,92.327 99.827,92.747 100.73,93.65 100.73,93.83 U2.19@100.75,93.85
  Bottom Layer w0.5: R15.2@107,92.35 107,84.027 107.5,83.527 v1(107.5,83.5)
  other v1: 107.5,81 108.5,81 109.5,81 110.5,81 109.465,82.215 107.5,82.25 108.5,82.25 110.5,82.25 108.5,83.5 109.5,83.5 110.5,83.5
B18V_SYNCIN: R10.2 U2.8 | length 2.4
  Bottom Layer w0.2: U2.8@103.75,97.15 103.75,97.85 104.573,98.673 R10.2@104.573,99.25
B18V_VCC: C16.2 R10.1 U2.14 | length 14.1
  Int2 (GND) w0.5: v1(103.5,92.5) 103.5,93.5 105.927,95.927 v1(105.927,100.677)
  Bottom Layer w0.2: U2.14@103.25,93.85 103.23,93.83 103.23,93.554 103.17,93.494 103.17,93.426 103.15,93.406 103.15,92.75 104.023,91.876 C16.2@104.023,90.5 ; R10.1@105.927,99.5 v1(105.927,100.677)
B18V_VIN: C25.1 R14.2 U2.20 | length 4.3
  Bottom Layer w0.2: R14.2@98,92.25 C25.1@98,93.8 98.8,93.8 99.75,94.75 U2.20@100.35,94.75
